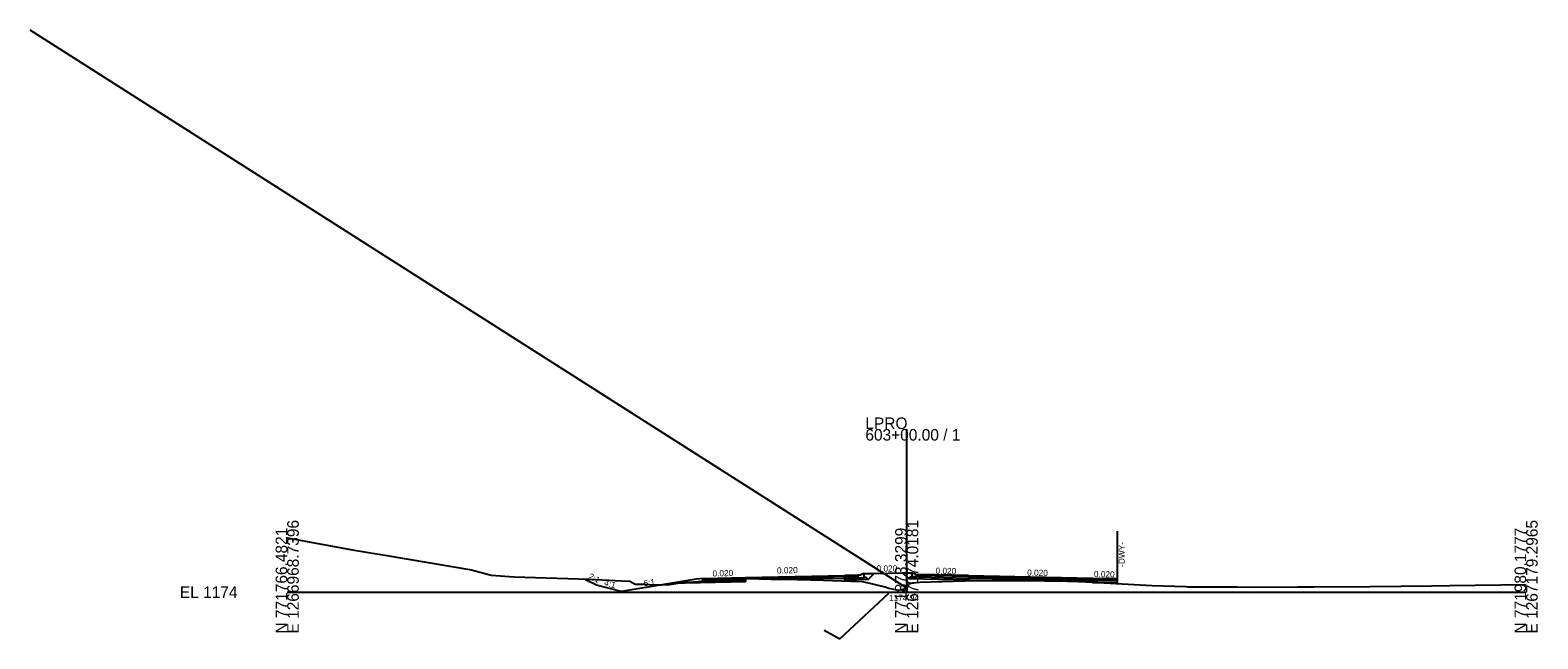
# Model space of a CAD drawing. Extents: x -3833 to 1267678, y -522 to 773248.
# Drawn here: x 937.8 to 1302.8, y 3988.7 to 4136 of the extents above; entities that cross this region are included whole.
import ezdxf

# ---------------------------------------------------------------- set-up
doc = ezdxf.new("R2010")
doc.units = 0
for name, color, linetype in [('Exist Cross Section Cell', 7, 'Continuous'), ('Exist XS Center Line Elevation Label', 7, 'Continuous'), ('Exist XS Ground Line', 7, 'Continuous'), ('Prop CMT DNC', 7, 'Continuous'), ('Prop CMT Pvmt Course 1', 7, 'Continuous'), ('Prop CMT Pvmt Course 2', 7, 'Continuous'), ('Prop CMT Pvmt Course 3', 7, 'Continuous'), ('Prop CMT Pvmt Course 4', 7, 'Continuous'), ('Prop CMT Shld Paved Course 1', 7, 'Continuous'), ('Prop CMT Shld Paved Course 2', 7, 'Continuous'), ('Prop CMT Shld Paved Course 4', 7, 'Continuous'), ('Prop CMT Slope Grass', 7, 'Continuous'), ('Prop CMT Subgrade Earthwork', 7, 'Continuous'), ('Prop Conc Curb and Gutter', 7, 'Continuous'), ('Prop Corridor Mesh Bottom', 7, 'Continuous'), ('Prop XS Ditch Slope Text', 7, 'Continuous'), ('Prop XS Finish Grade', 7, 'Continuous'), ('Prop XS Label Text', 7, 'Continuous'), ('Prop XS SE Text', 7, 'Continuous'), ('Prop XS Shear Point Element', 7, 'Continuous'), ('Prop XS Shear Point Label', 7, 'Continuous'), ('Scratch_Level_1', 7, 'Continuous'), ('Scratch_Level_5', 7, 'Continuous')]:
    doc.layers.add(name, color=color, linetype=linetype)

msp = doc.modelspace()

# ---------------------------------------------------------------- linework, layer by layer
at = {"layer": 'Exist Cross Section Cell'}
for p, q in [((1150, 4000), (1150, 4039.5)), ((1000, 4000), (1150, 4000)), ((1150, 4000), (1300, 4000))]:
    msp.add_line(p, q, dxfattribs=at)
at = {"layer": 'Exist XS Ground Line'}
for p, q in [((1000, 4013.17), (1000.96, 4013.04)), ((1000.96, 4013.04), (1007.01, 4011.89)), ((1007.01, 4011.89), (1016.2, 4010.21)), ((1016.2, 4010.21), (1018.2, 4009.83)), ((1018.2, 4009.83), (1023.66, 4008.95)), ((1023.66, 4008.95), (1044.63, 4005.42)), ((1044.63, 4005.42), (1049.37, 4004.1)), ((1049.37, 4004.1), (1054.94, 4003.72)), ((1054.94, 4003.72), (1073.14, 4003.15)), ((1073.14, 4003.15), (1080.95, 4002.74)), ((1080.95, 4002.74), (1082.93, 4002.71)), ((1082.93, 4002.71), (1084.29, 4001.94)), ((1084.29, 4001.94), (1086.68, 4001.97)), ((1086.68, 4001.97), (1088.66, 4001.82)), ((1088.66, 4001.82), (1090.71, 4001.78)), ((1090.71, 4001.78), (1092.59, 4001.89)), ((1092.59, 4001.89), (1095.61, 4002.39)), ((1095.61, 4002.39), (1096.33, 4002.41)), ((1096.33, 4002.41), (1097.3, 4002.47)), ((1097.3, 4002.47), (1106.96, 4003.13)), ((1106.96, 4003.13), (1109.01, 4003.22)), ((1109.01, 4003.22), (1111.44, 4003.29)), ((1111.44, 4003.29), (1117.07, 4003.17)), ((1117.07, 4003.17), (1123.49, 4003.07)), ((1123.49, 4003.07), (1129.85, 4002.89)), ((1129.85, 4002.89), (1136.47, 4002.7)), ((1136.47, 4002.7), (1137.86, 4002.68)), ((1137.86, 4002.68), (1139.2, 4002.63)), ((1139.2, 4002.63), (1139.96, 4002.45)), ((1139.96, 4002.45), (1140.32, 4002.38)), ((1140.32, 4002.38), (1144.39, 4001.4)), ((1144.39, 4001.4), (1144.76, 4001.28)), ((1150.13, 4001.01), (1150.51, 4002.01)), ((1150.51, 4002.01), (1151.46, 4002.24)), ((1151.46, 4002.24), (1153.2, 4002.44)), ((1153.2, 4002.44), (1164.11, 4002.78)), ((1164.11, 4002.78), (1165.04, 4002.81)), ((1165.04, 4002.81), (1176.17, 4002.85)), ((1176.17, 4002.85), (1176.48, 4002.85)), ((1176.48, 4002.85), (1177.74, 4002.84)), ((1177.74, 4002.84), (1188.93, 4002.7)), ((1188.93, 4002.7), (1189.79, 4002.66)), ((1189.79, 4002.66), (1193.45, 4002.48)), ((1193.45, 4002.48), (1209.45, 4001.6)), ((1209.45, 4001.6), (1214.89, 4001.47)), ((1214.89, 4001.47), (1217.64, 4001.36)), ((1248.62, 4001.3), (1262.21, 4001.41)), ((1262.21, 4001.41), (1277.09, 4001.55)), ((1277.09, 4001.55), (1281.5, 4001.59)), ((1281.5, 4001.59), (1293.85, 4001.75)), ((1293.85, 4001.75), (1300, 4001.84)), ((1144.76, 4001.28), (1145.7, 4000.95)), ((1145.7, 4000.95), (1147.98, 4000.53)), ((1147.98, 4000.53), (1150.13, 4001.01)), ((1217.64, 4001.36), (1218.14, 4001.33)), ((1218.14, 4001.33), (1229.99, 4001.31)), ((1229.99, 4001.31), (1233.72, 4001.26)), ((1233.72, 4001.26), (1244.71, 4001.31)), ((1244.71, 4001.31), (1248.62, 4001.3))]:
    msp.add_line(p, q, dxfattribs=at)
at = {"layer": 'Prop CMT Pvmt Course 1'}
for p, q in [((1111, 4003.55), (1135, 4004.03)), ((1135, 4003.78), (1111, 4003.3)), ((1111, 4003.3), (1111, 4003.55)), ((1111, 4003.55), (1111, 4003.55)), ((1111, 4003.3), (1111, 4003.55)), ((1111, 4003.55), (1111, 4003.55)), ((1135, 4004.03), (1135, 4004.03)), ((1135, 4004.03), (1135, 4004.03)), ((1135, 4004.03), (1135, 4003.78)), ((1135, 4003.78), (1135, 4003.78)), ((1165, 4004.03), (1195, 4003.43)), ((1165, 4003.78), (1195, 4003.18)), ((1195, 4003.18), (1195, 4003.43)), ((1195, 4003.43), (1195, 4003.43)), ((1195, 4003.43), (1195, 4003.43)), ((1195, 4003.43), (1201, 4003.31)), ((1195, 4003.18), (1201, 4003.06))]:
    msp.add_line(p, q, dxfattribs=at)
at = {"layer": 'Prop CMT Pvmt Course 2'}
for p, q in [((1138.2, 4003.84), (1135, 4003.78)), ((1135, 4003.78), (1135, 4003.78)), ((1135, 4003.44), (1138.2, 4003.51)), ((1135, 4003.45), (1135, 4003.44)), ((1150, 4004.08), (1150, 4004.08)), ((1150, 4004.08), (1150, 4004.08)), ((1150, 4003.75), (1150, 4003.75)), ((1150, 4003.75), (1150, 4003.75)), ((1165, 4003.78), (1152.87, 4004.02)), ((1152.87, 4003.69), (1165, 4003.44)), ((1165, 4003.78), (1165, 4003.78)), ((1165, 4003.44), (1165, 4003.44)), ((1195, 4002.85), (1201, 4002.73))]:
    msp.add_line(p, q, dxfattribs=at)
at = {"layer": 'Prop CMT Pvmt Course 3'}
for p, q in [((1138.2, 4003.51), (1138.2, 4003.51)), ((1138.2, 4003.51), (1138.2, 4003.51)), ((1140.22, 4003.54), (1139.71, 4003.53)), ((1140.66, 4003.1), (1140.22, 4003.54)), ((1140.5, 4003.26), (1140.49, 4003.27)), ((1150.41, 4003.28), (1150.86, 4003.73)), ((1150.86, 4003.73), (1151.36, 4003.72))]:
    msp.add_line(p, q, dxfattribs=at)
at = {"layer": 'Prop CMT Pvmt Course 4'}
for p, q in [((1135, 4002.74), (1135, 4003.45)), ((1135, 4003.45), (1135, 4003.45)), ((1135, 4003.45), (1135, 4003.44)), ((1138.2, 4002.72), (1138.2, 4002.72)), ((1150, 4003.75), (1150, 4003.75)), ((1150, 4003.75), (1150, 4003.75)), ((1165, 4003.44), (1165, 4003.44)), ((1165, 4003.44), (1165, 4003.44)), ((1165, 4003.44), (1165, 4002.81)), ((1201, 4002.73), (1195, 4002.85))]:
    msp.add_line(p, q, dxfattribs=at)
at = {"layer": 'Prop CMT Shld Paved Course 1'}
for p, q in [((1100.74, 4003.09), (1101, 4003.35)), ((1111, 4003.3), (1100.74, 4003.09)), ((1101, 4003.35), (1111, 4003.55)), ((1101, 4003.35), (1101, 4003.35)), ((1111, 4003.55), (1111, 4003.55)), ((1111, 4003.55), (1111, 4003.55)), ((1111, 4003.55), (1111, 4003.3)), ((1111, 4003.3), (1111, 4003.3)), ((1138.2, 4004.09), (1135, 4004.03)), ((1135, 4004.03), (1135, 4004.03)), ((1135, 4004.03), (1135, 4003.78)), ((1150, 4004.08), (1150, 4004.08)), ((1150, 4004.08), (1150, 4004.08)), ((1165, 4004.03), (1152.87, 4004.27)), ((1165, 4003.78), (1165, 4004.03)), ((1165, 4004.03), (1165, 4004.03))]:
    msp.add_line(p, q, dxfattribs=at)
at = {"layer": 'Prop CMT Shld Paved Course 2'}
for p, q in [((1100.4, 4002.75), (1100.74, 4003.09)), ((1111, 4002.96), (1100.4, 4002.75)), ((1100.74, 4003.09), (1111, 4003.3)), ((1100.74, 4003.09), (1100.74, 4003.09)), ((1111, 4003.3), (1111.44, 4003.31)), ((1111.44, 4003.31), (1111, 4003.3)), ((1111, 4003.3), (1111, 4003.3)), ((1111, 4003.3), (1111, 4003.3)), ((1111, 4003.3), (1111, 4002.96)), ((1111, 4003.3), (1111, 4003.3)), ((1111, 4003.3), (1111, 4003.3)), ((1111, 4003.3), (1111, 4003.27)), ((1111, 4003.27), (1111, 4003.27)), ((1111, 4002.96), (1111, 4002.96)), ((1117.07, 4003.42), (1111.44, 4003.31)), ((1111.44, 4003.31), (1112.22, 4003.32)), ((1111.44, 4003.31), (1111.44, 4003.31)), ((1111.44, 4003.31), (1111.44, 4003.31)), ((1111.44, 4003.31), (1111.44, 4003.31)), ((1111.44, 4003.31), (1111.44, 4003.31)), ((1112.22, 4003.32), (1112.22, 4003.32)), ((1112.22, 4003.32), (1117.07, 4003.22)), ((1123.49, 4003.55), (1117.07, 4003.42)), ((1117.07, 4003.42), (1117.07, 4003.42)), ((1117.07, 4003.22), (1117.07, 4003.22)), ((1117.07, 4003.22), (1120.85, 4003.16)), ((1120.85, 4003.16), (1123.49, 4003.21)), ((1129.85, 4003.67), (1123.49, 4003.55)), ((1123.49, 4003.55), (1123.49, 4003.55)), ((1123.49, 4003.21), (1129.85, 4003.34)), ((1123.49, 4003.21), (1123.49, 4003.21)), ((1123.49, 4003.21), (1123.49, 4003.21)), ((1135, 4003.78), (1129.85, 4003.67)), ((1129.85, 4003.67), (1129.85, 4003.67)), ((1129.85, 4003.34), (1135, 4003.44)), ((1129.85, 4003.34), (1129.85, 4003.34)), ((1135, 4003.44), (1135, 4003.78)), ((1135, 4003.78), (1135, 4003.78)), ((1165, 4003.78), (1165, 4003.78)), ((1165, 4003.78), (1165, 4003.44)), ((1165, 4003.44), (1165.04, 4003.44)), ((1165.04, 4003.78), (1165.04, 4003.78)), ((1165.04, 4003.44), (1165.04, 4003.44)), ((1165.04, 4003.44), (1176.17, 4003.22)), ((1176.48, 4003.55), (1176.17, 4003.55)), ((1176.17, 4003.55), (1176.17, 4003.55)), ((1176.17, 4003.22), (1176.17, 4003.22)), ((1176.17, 4003.22), (1176.48, 4003.21)), ((1177.64, 4003.52), (1176.48, 4003.55)), ((1176.48, 4003.21), (1177.64, 4003.19)), ((1177.74, 4003.52), (1177.64, 4003.52)), ((1177.64, 4003.19), (1177.74, 4003.19)), ((1188.93, 4003.3), (1177.74, 4003.52)), ((1177.74, 4003.52), (1177.74, 4003.52)), ((1177.74, 4003.19), (1177.74, 4003.19)), ((1177.74, 4003.19), (1188.93, 4002.97)), ((1189.67, 4003.28), (1188.93, 4003.3)), ((1188.93, 4003.3), (1188.93, 4003.3)), ((1188.93, 4002.97), (1188.93, 4002.97)), ((1188.93, 4002.97), (1189.67, 4002.95)), ((1189.79, 4003.28), (1189.67, 4003.28)), ((1189.67, 4003.28), (1189.67, 4003.28)), ((1189.67, 4002.95), (1189.67, 4002.95)), ((1189.67, 4002.95), (1189.79, 4002.95)), ((1193.45, 4003.21), (1189.79, 4003.28)), ((1189.79, 4003.28), (1189.79, 4003.28)), ((1189.79, 4003.28), (1189.79, 4003.28)), ((1189.79, 4002.95), (1189.79, 4002.95)), ((1189.79, 4002.95), (1189.79, 4002.95)), ((1189.79, 4002.95), (1193.45, 4002.87)), ((1193.45, 4003.21), (1193.45, 4003.21)), ((1193.45, 4003.21), (1193.45, 4003.21)), ((1193.45, 4002.87), (1193.45, 4002.87)), ((1193.45, 4002.87), (1193.45, 4002.87)), ((1193.45, 4002.87), (1195, 4002.84)), ((1195, 4002.84), (1195, 4003.18)), ((1195, 4003.18), (1195, 4003.18)), ((1195, 4003.18), (1195, 4003.18)), ((1195, 4002.84), (1195, 4002.84))]:
    msp.add_line(p, q, dxfattribs=at)
at = {"layer": 'Prop CMT Shld Paved Course 4'}
for p, q in [((1099.94, 4002.28), (1100.4, 4002.75)), ((1111, 4002.51), (1099.94, 4002.28)), ((1100.4, 4002.75), (1100.9, 4002.76)), ((1100.9, 4002.76), (1111, 4002.96)), ((1111, 4002.96), (1111, 4002.51))]:
    msp.add_line(p, q, dxfattribs=at)
at = {"layer": 'Prop CMT Slope Grass'}
for p, q in [((1099, 4003.19), (1092.72, 4002.14)), ((1101, 4003.35), (1099, 4003.19)), ((1139.71, 4004.52), (1142.12, 4004.56)), ((1149.03, 4004.67), (1151.36, 4004.7))]:
    msp.add_line(p, q, dxfattribs=at)
at = {"layer": 'Prop CMT Subgrade Earthwork'}
for p, q in [((1111, 4002.51), (1092.72, 4002.14)), ((1111, 4003.28), (1111, 4002.51)), ((1140.66, 4003.1), (1135, 4002.99)), ((1135, 4002.99), (1135, 4002.74)), ((1140.66, 4003.1), (1142.12, 4004.56)), ((1150.41, 4003.28), (1149.03, 4004.67)), ((1150.41, 4003.28), (1165, 4002.99)), ((1165, 4002.99), (1165, 4002.81)), ((1195.1, 4002.39), (1201, 4002.27)), ((1201, 4002.27), (1201, 4002.06))]:
    msp.add_line(p, q, dxfattribs=at)
at = {"layer": 'Prop Conc Curb and Gutter'}
for p, q in [((1138.95, 4004.1), (1138.2, 4004.09)), ((1138.2, 4004.09), (1138.2, 4004.09)), ((1138.2, 4004.09), (1138.2, 4003.51)), ((1138.2, 4004.09), (1138.2, 4004.09)), ((1138.2, 4003.51), (1139.71, 4003.53)), ((1138.2, 4003.51), (1138.2, 4003.51)), ((1138.96, 4004.27), (1138.95, 4004.27)), ((1138.95, 4004.27), (1138.95, 4004.11)), ((1138.95, 4004.11), (1138.95, 4004.1)), ((1139.71, 4004.52), (1138.96, 4004.27)), ((1139.71, 4003.56), (1139.71, 4004.52)), ((1139.71, 4003.53), (1139.71, 4003.56)), ((1151.36, 4003.72), (1151.36, 4004.7)), ((1151.36, 4004.7), (1151.36, 4004.7)), ((1151.36, 4004.7), (1151.36, 4004.7)), ((1151.36, 4004.7), (1152.12, 4004.45)), ((1151.37, 4003.72), (1151.36, 4003.72)), ((1152.87, 4003.69), (1151.37, 4003.72)), ((1152.12, 4004.45), (1152.12, 4004.45)), ((1152.12, 4004.45), (1152.12, 4004.29)), ((1152.12, 4004.29), (1152.87, 4004.27)), ((1152.12, 4004.29), (1152.12, 4004.29)), ((1152.87, 4004.27), (1152.87, 4004.27)), ((1152.87, 4004.27), (1152.87, 4003.69))]:
    msp.add_line(p, q, dxfattribs=at)
at = {"layer": 'Prop Corridor Mesh Bottom'}
for p, q in [((1111, 4003.55), (1111, 4003.3)), ((1111, 4003.55), (1111, 4003.3)), ((1165, 4004.03), (1165, 4003.78))]:
    msp.add_line(p, q, dxfattribs=at)
at = {"layer": 'Prop XS Finish Grade'}
for p, q in [((1074.9, 4001.69), (1071.89, 4003.19)), ((1080.9, 4000.19), (1074.9, 4001.69)), ((1092.72, 4002.14), (1081, 4000.19)), ((1142.12, 4004.56), (1149.03, 4004.67)), ((1080.95, 4000.19), (1080.9, 4000.19)), ((1081, 4000.19), (1080.95, 4000.19))]:
    msp.add_line(p, q, dxfattribs=at)
at = {"layer": 'Prop XS Shear Point Element'}
msp.add_line((1201, 4014.81), (1201, 4002.06), dxfattribs=at)
at = {"layer": 'Scratch_Level_1'}
msp.add_line((1150, 4000.98), (937.75, 4136.04), dxfattribs=at)
at = {"layer": 'Scratch_Level_5'}
for p, q in [((1133.8, 3988.72), (1145.65, 3999.74)), ((1130.01, 3990.82), (1133.8, 3988.72))]:
    msp.add_line(p, q, dxfattribs=at)

# ---------------------------------------------------------------- texts
at = {"layer": 'Exist Cross Section Cell'}
for s, p in [('LPRO', (1140, 4039.5)), ('603+00.00 / 1', (1140, 4036.7)), ('EL 1174', (974, 3998.6))]:
    msp.add_text(s, height=2.8, dxfattribs=at).set_placement(p)
for s, p in [('E 1266968.7396', (1002.8, 3990)), ('E 1267074.0181', (1152.8, 3990)), ('E 1267179.2965', (1302.8, 3990)), ('N 771766.4821', (1000, 3990)), ('N 771873.3299', (1150, 3990)), ('N 771980.1777', (1300, 3990))]:
    msp.add_text(s, height=2.8, rotation=90, dxfattribs=at).set_placement(p)
at = {"layer": 'Exist XS Center Line Elevation Label'}
msp.add_text('1174.94', height=1.5, dxfattribs=at).set_placement((1145.72, 3997.88))
at = {"layer": 'Prop CMT DNC'}
for p in [(1065.21, 4003.45), (1101, 4003.35), (1111, 4003.55), (1111, 4003.55), (1111, 4003.55), (1111, 4003.55), (1135, 4004.03), (1135, 4004.03), (1138.95, 4004.1), (1152.12, 4004.29), (1165, 4004.03), (1165, 4004.03), (1201, 4003.31), (1201, 4003.31), (1080.95, 4000.19), (1081, 4000.19), (1242.47, 4001.35)]:
    msp.add_text('X', height=0.00025, dxfattribs=at).set_placement(p)
at = {"layer": 'Prop XS Ditch Slope Text'}
for s, rotation, p in [('2:1', 333.2561, (1072.76, 4003.35)), ('4:1', 345.1523, (1076.63, 4001.63)), ('6:1', 6.8342, (1086.39, 4001.43))]:
    msp.add_text(s, height=1.5, rotation=rotation, dxfattribs=at).set_placement(p)
at = {"layer": 'Prop XS Label Text'}
msp.add_text('0.020', height=0.15, rotation=358.8542, dxfattribs=at).set_placement((1179.79, 4004.43))
at = {"layer": 'Prop XS SE Text'}
for rotation, p in [(1.397, (1103, 4003.8)), (1.397, (1118.61, 4004.51)), (0.2693, (1142.71, 4004.98)), (358.8542, (1156.98, 4004.45)), (358.8542, (1179.16, 4004)), (358.8542, (1195.33, 4003.67))]:
    msp.add_text('0.020', height=1.5, rotation=rotation, dxfattribs=at).set_placement(p)
at = {"layer": 'Prop XS Shear Point Label'}
msp.add_text('-DWY-', height=1.5, rotation=90, dxfattribs=at).set_placement((1202.81, 4006.12))

doc.saveas('drawing.dxf')
